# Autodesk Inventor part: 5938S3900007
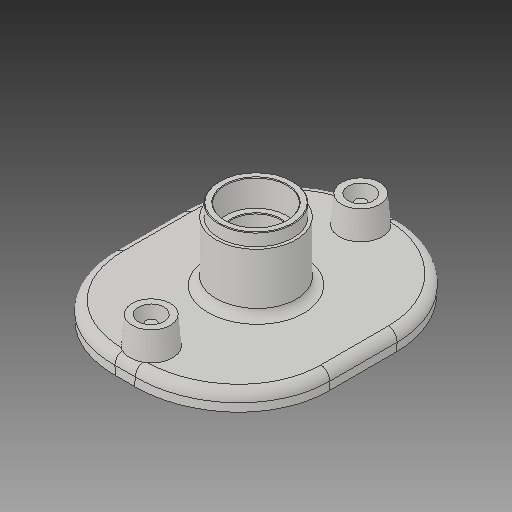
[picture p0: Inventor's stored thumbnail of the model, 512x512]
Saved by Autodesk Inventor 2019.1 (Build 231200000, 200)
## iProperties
Created: 2017-08
Part Number: 5938S3900007
Material: Generic
Description: PLASSON SENSOR ADAPTOR WITH STAINLESS STEEL THREAD 18''48''IPSx3/4''
Document SubType Name: Modeling
Designer: Кирилл
Density: 1 g/cm^3
Appearance: Default
Author: Кирилл
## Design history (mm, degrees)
derived "5938S.ipt"
feature "Solid1::5938S.ipt"
feature "Solid2::5938S.ipt"
feature "Solid3::5938S.ipt"
tag "TaggingFeature1"
body "Solid1"
other parameters: "d0" = 1213.7, "d1" = 84.836, "d3" = 102.87, "d4" = 0, "d5" = 38.1762, "d11" = 788.905, "d38" = 3.6411, "d40" = 624.376, "d41" = 15, "d42" = 41.148, "d46" = 5 deg, "d47" = 4, "d51" = 14, "d52" = 0, "d53" = 3, "d54" = 0, "d75" = 0, "d77" = 0, "d78" = 0.24117, "d82" = 35.052, "d83" = 31.3521, "d84" = 28.9404, "d85" = 19.2936, "d86" = 24.117, "d89" = 10.5156, "d90" = 4.90728, "d95" = 3.175, "d97" = 360 deg, "d99" = 7.0104, "d_" = 1213.7, "B_" = 84.836, "H_" = 35.052, "L_" = 102.87, "G_" = 24.117
